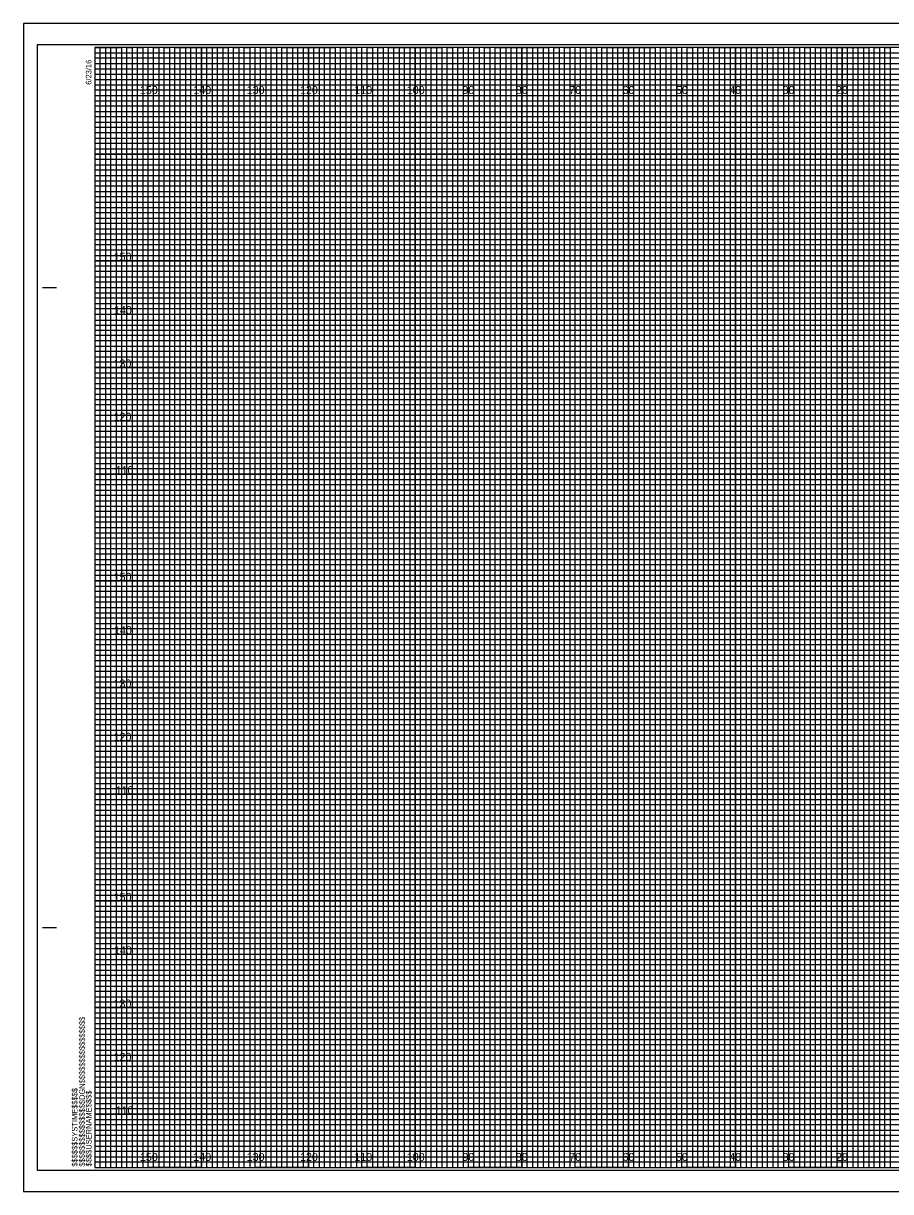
# Model space of a CAD drawing. Extents: x -13 to 323, y -5 to 2634.
# Drawn here: x -13.4 to 149.1, y 215.5 to 434.5 of the extents above; entities that cross this region are included whole.
import ezdxf

# ---------------------------------------------------------------- set-up
doc = ezdxf.new("R2010")
doc.units = 0
for name, color, linetype in [('Exist Cross Section Cell', 7, 'Continuous'), ('Exist XS Center Line Elevation Label', 7, 'Continuous'), ('Exist XS Ground Line', 7, 'Continuous'), ('Prop CMT Pvmt Course 1 Wedge', 7, 'Continuous'), ('Prop CMT Pvmt Course 2', 7, 'Continuous'), ('Prop CMT Pvmt Course 2 Wedge', 7, 'Continuous'), ('Prop CMT Pvmt Course 3', 7, 'Continuous'), ('Prop CMT Shld Paved Course 1', 7, 'Continuous'), ('Prop CMT Shld Paved Course 2', 7, 'Continuous'), ('Prop CMT Subgrade Earthwork', 7, 'Continuous'), ('Scratch_Level_0', 7, 'Continuous')]:
    doc.layers.add(name, color=color, linetype=linetype)

msp = doc.modelspace()

# ---------------------------------------------------------------- linework, layer by layer
at = {"layer": 'Exist XS Center Line Elevation Label'}
for points in [[(0, 430), (5, 430), (5, 220), (15, 220), (15, 430), (25, 430), (25, 220), (35, 220), (35, 430), (45, 430), (45, 220), (55, 220), (55, 430), (65, 430), (65, 220), (75, 220), (75, 430), (85, 430), (85, 220), (95, 220), (95, 430), (105, 430), (105, 220), (115, 220), (115, 430), (125, 430), (125, 220), (135, 220), (135, 430), (145, 430), (145, 220), (155, 220)], [(0, 425), (275, 425)], [(0, 405), (320, 405), (320, 415), (0, 415)], [(0, 385), (320, 385), (320, 395), (0, 395)], [(0, 365), (320, 365), (320, 375), (0, 375)], [(0, 345), (320, 345), (320, 355), (0, 355)], [(0, 325), (320, 325), (320, 335), (0, 335)], [(0, 305), (320, 305), (320, 315), (0, 315)], [(0, 285), (320, 285), (320, 295), (0, 295)], [(0, 265), (320, 265), (320, 275), (0, 275)], [(0, 245), (320, 245), (320, 255), (0, 255)], [(0, 225), (320, 225), (320, 235), (0, 235)]]:
    msp.add_lwpolyline(points, dxfattribs=at)
at = {"layer": 'Exist XS Ground Line'}
for p, q in [((10, 430), (0, 430)), ((10, 220), (10, 430)), ((30, 430), (20, 430)), ((20, 430), (20, 220)), ((30, 220), (30, 430)), ((50, 430), (40, 430)), ((40, 430), (40, 220)), ((50, 220), (50, 430)), ((70, 430), (60, 430)), ((60, 430), (60, 220)), ((70, 220), (70, 430)), ((90, 430), (80, 430)), ((80, 430), (80, 220)), ((90, 220), (90, 430)), ((110, 430), (100, 430)), ((100, 430), (100, 220)), ((110, 220), (110, 430)), ((130, 430), (120, 430)), ((120, 430), (120, 220)), ((130, 220), (130, 430)), ((150, 430), (140, 430)), ((140, 430), (140, 220)), ((20, 220), (10, 220)), ((40, 220), (30, 220)), ((60, 220), (50, 220)), ((80, 220), (70, 220)), ((100, 220), (90, 220)), ((120, 220), (110, 220)), ((140, 220), (130, 220))]:
    msp.add_line(p, q, dxfattribs=at)
for points in [[(0, 420), (320, 420), (320, 410), (0, 410)], [(0, 400), (320, 400), (320, 390), (0, 390)], [(0, 380), (320, 380), (320, 370), (0, 370)], [(0, 360), (320, 360), (320, 350), (0, 350)], [(0, 340), (320, 340), (320, 330), (0, 330)], [(0, 320), (320, 320), (320, 310), (0, 310)], [(0, 300), (320, 300), (320, 290), (0, 290)], [(0, 280), (320, 280), (320, 270), (0, 270)], [(0, 260), (320, 260), (320, 250), (0, 250)], [(0, 240), (320, 240), (320, 230), (0, 230)]]:
    msp.add_lwpolyline(points, dxfattribs=at)
at = {"layer": 'Prop CMT Pvmt Course 1 Wedge'}
for p, q in [((323.3, 434.5), (-13.4, 434.5)), ((-13.4, 434.5), (-13.4, 215.5)), ((-13.4, 215.5), (323.3, 215.5))]:
    msp.add_line(p, q, dxfattribs=at)
at = {"layer": 'Prop CMT Pvmt Course 2'}
msp.add_lwpolyline([(-13.4, 215.5), (323.3, 215.5), (323.3, 434.5), (-13.4, 434.5)], close=True, dxfattribs=at)
at = {"layer": 'Prop CMT Pvmt Course 3'}
msp.add_lwpolyline([(-10.8, 219.5), (322.4, 219.5), (322.4, 430.5), (-10.8, 430.5)], close=True, dxfattribs=at)
at = {"layer": 'Prop CMT Shld Paved Course 1'}
for p, q in [((-9.8, 385), (-7.3, 385)), ((-9.7, 385), (-7.2, 385)), ((-9.8, 265), (-7.3, 265)), ((-9.7, 265), (-7.2, 265)), ((0, 220), (0, 220)), ((0, 220), (0, 220)), ((0, 220), (0, 220)), ((0, 220), (0, 220)), ((0, 220), (0, 220)), ((0, 220), (0, 220)), ((0, 220), (0, 220))]:
    msp.add_line(p, q, dxfattribs=at)
msp.add_lwpolyline([(320, 430), (0, 430), (0, 220), (320, 220)], close=True, dxfattribs=at)
at = {"layer": 'Prop CMT Shld Paved Course 2'}
for points in [[(0, 220), (1, 220), (1, 430), (2, 430), (2, 220)], [(2, 220), (3, 220), (3, 430), (4, 430), (4, 220)], [(5, 220), (6, 220), (6, 430), (7, 430), (7, 220)], [(7, 220), (8, 220), (8, 430), (9, 430), (9, 220)], [(10, 220), (11, 220), (11, 430), (12, 430), (12, 220)], [(12, 220), (13, 220), (13, 430), (14, 430), (14, 220)], [(15, 220), (16, 220), (16, 430), (17, 430), (17, 220)], [(17, 220), (18, 220), (18, 430), (19, 430), (19, 220)], [(20, 220), (21, 220), (21, 430), (22, 430), (22, 220)], [(22, 220), (23, 220), (23, 430), (24, 430), (24, 220)], [(25, 220), (26, 220), (26, 430), (27, 430), (27, 220)], [(27, 220), (28, 220), (28, 430), (29, 430), (29, 220)], [(30, 220), (31, 220), (31, 430), (32, 430), (32, 220)], [(32, 220), (33, 220), (33, 430), (34, 430), (34, 220)], [(35, 220), (36, 220), (36, 430), (37, 430), (37, 220)], [(37, 220), (38, 220), (38, 430), (39, 430), (39, 220)], [(40, 220), (41, 220), (41, 430), (42, 430), (42, 220)], [(42, 220), (43, 220), (43, 430), (44, 430), (44, 220)], [(45, 220), (46, 220), (46, 430), (47, 430), (47, 220)], [(47, 220), (48, 220), (48, 430), (49, 430), (49, 220)], [(50, 220), (51, 220), (51, 430), (52, 430), (52, 220)], [(52, 220), (53, 220), (53, 430), (54, 430), (54, 220)], [(55, 220), (56, 220), (56, 430), (57, 430), (57, 220)], [(57, 220), (58, 220), (58, 430), (59, 430), (59, 220)], [(60, 220), (61, 220), (61, 430), (62, 430), (62, 220)], [(62, 220), (63, 220), (63, 430), (64, 430), (64, 220)], [(65, 220), (66, 220), (66, 430), (67, 430), (67, 220)], [(67, 220), (68, 220), (68, 430), (69, 430), (69, 220)], [(70, 220), (71, 220), (71, 430), (72, 430), (72, 220)], [(72, 220), (73, 220), (73, 430), (74, 430), (74, 220)], [(75, 220), (76, 220), (76, 430), (77, 430), (77, 220)], [(77, 220), (78, 220), (78, 430), (79, 430), (79, 220)], [(80, 220), (81, 220), (81, 430), (82, 430), (82, 220)], [(82, 220), (83, 220), (83, 430), (84, 430), (84, 220)], [(85, 220), (86, 220), (86, 430), (87, 430), (87, 220)], [(87, 220), (88, 220), (88, 430), (89, 430), (89, 220)], [(90, 220), (91, 220), (91, 430), (92, 430), (92, 220)], [(92, 220), (93, 220), (93, 430), (94, 430), (94, 220)], [(95, 220), (96, 220), (96, 430), (97, 430), (97, 220)], [(97, 220), (98, 220), (98, 430), (99, 430), (99, 220)], [(100, 220), (101, 220), (101, 430), (102, 430), (102, 220)], [(102, 220), (103, 220), (103, 430), (104, 430), (104, 220)], [(105, 220), (106, 220), (106, 430), (107, 430), (107, 220)], [(107, 220), (108, 220), (108, 430), (109, 430), (109, 220)], [(110, 220), (111, 220), (111, 430), (112, 430), (112, 220)], [(112, 220), (113, 220), (113, 430), (114, 430), (114, 220)], [(115, 220), (116, 220), (116, 430), (117, 430), (117, 220)], [(117, 220), (118, 220), (118, 430), (119, 430), (119, 220)], [(120, 220), (121, 220), (121, 430), (122, 430), (122, 220)], [(122, 220), (123, 220), (123, 430), (124, 430), (124, 220)], [(125, 220), (126, 220), (126, 430), (127, 430), (127, 220)], [(127, 220), (128, 220), (128, 430), (129, 430), (129, 220)], [(130, 220), (131, 220), (131, 430), (132, 430), (132, 220)], [(132, 220), (133, 220), (133, 430), (134, 430), (134, 220)], [(135, 220), (136, 220), (136, 430), (137, 430), (137, 220)], [(137, 220), (138, 220), (138, 430), (139, 430), (139, 220)], [(140, 220), (141, 220), (141, 430), (142, 430), (142, 220)], [(142, 220), (143, 220), (143, 430), (144, 430), (144, 220)], [(145, 220), (146, 220), (146, 430), (147, 430), (147, 220)], [(147, 220), (148, 220), (148, 430), (149, 430), (149, 220)]]:
    msp.add_lwpolyline(points, dxfattribs=at)
at = {"layer": 'Prop CMT Subgrade Earthwork'}
for p, q in [((10, 220), (10, 430)), ((20, 220), (20, 430)), ((30, 220), (30, 430)), ((40, 220), (40, 430)), ((50, 220), (50, 430)), ((60, 220), (60, 430)), ((70, 220), (70, 430)), ((80, 220), (80, 430)), ((90, 220), (90, 430)), ((100, 220), (100, 430)), ((110, 220), (110, 430)), ((120, 220), (120, 430)), ((130, 220), (130, 430)), ((140, 220), (140, 430)), ((0, 420), (320, 420)), ((0, 410), (320, 410)), ((0, 400), (320, 400)), ((0, 390), (320, 390)), ((0, 380), (320, 380)), ((0, 370), (320, 370)), ((0, 360), (320, 360)), ((0, 350), (320, 350)), ((0, 340), (320, 340)), ((0, 330), (320, 330)), ((0, 320), (320, 320)), ((0, 310), (320, 310)), ((0, 300), (320, 300)), ((0, 290), (320, 290)), ((0, 280), (320, 280)), ((0, 270), (320, 270)), ((0, 260), (320, 260)), ((0, 250), (320, 250)), ((0, 240), (320, 240)), ((0, 230), (320, 230))]:
    msp.add_line(p, q, dxfattribs=at)
at = {"layer": 'Scratch_Level_0'}
for p, q in [((0, 429), (260, 429)), ((260, 427.98), (0, 427.98)), ((0, 427.98), (0, 427)), ((0, 427), (260, 427)), ((260, 425.89), (0, 425.89)), ((0, 425.89), (0, 424)), ((0, 424), (320, 424))]:
    msp.add_line(p, q, dxfattribs=at)
for points in [[(0, 423), (270, 423), (320, 423), (320, 422), (0, 422)], [(0, 421), (320, 421), (320, 419), (0, 419)], [(0, 418), (320, 418), (320, 417), (0, 416.98)], [(0, 416), (320, 416), (320, 414), (0, 414)], [(0, 413), (320, 413), (320, 412), (0, 412)], [(0, 411), (320, 411), (320, 409), (0, 409)], [(0, 408), (320, 408), (320, 407), (0, 407)], [(0, 406), (320, 406), (320, 404), (0, 404)], [(0, 403), (320, 403), (320, 402), (0, 402)], [(0, 401), (320, 401), (320, 399), (0, 399)], [(0, 398), (320, 398), (320, 397), (0, 397)], [(0, 396), (320, 396), (320, 393.95), (320, 393), (320, 392), (0, 392)], [(0, 394), (320, 394), (320, 393), (0, 393)], [(0, 391), (320, 391), (320, 389), (0, 389.03)], [(0, 389.03), (320, 389), (320, 388), (0, 388)], [(0, 387), (320, 387), (320, 386), (0, 386)], [(0, 384), (320, 384), (320, 383), (0, 383)], [(0, 382), (320, 382), (320, 381), (0, 381)], [(-0.07, 378.89), (320, 378.89), (320, 377.88), (-0.07, 377.88)], [(0, 377), (320, 377), (320, 376), (0, 376)], [(0, 374), (320, 374), (320, 373), (0, 373)], [(0, 372), (320, 372), (320, 371), (0, 371)], [(0, 369), (320, 369), (320, 368), (0, 368)], [(0, 367), (320, 367), (320, 366), (0, 366)], [(0, 364), (320, 364), (320, 363), (0, 363)], [(0, 362), (320, 362), (320, 361), (0, 361)], [(0, 359), (320, 359), (319.99, 357.98), (0, 358)], [(0, 357), (320, 357), (320, 356), (0, 356)], [(0, 354), (320, 354), (320, 353), (0, 353)], [(0, 352), (320, 352), (320, 351), (0, 351)], [(0, 349), (320, 349), (320, 348), (0, 348)], [(0, 347), (320, 347), (320, 346), (0, 346)], [(0, 344), (320, 344), (320, 343), (0, 343)], [(0, 342), (320, 342), (320, 341), (0, 341)], [(0, 339), (320, 339), (320, 338), (0, 338)], [(0, 336.99), (320.07, 336.91), (320, 336), (0, 336)], [(0, 334), (320, 334), (320, 333), (0, 333)], [(0, 332), (320, 332), (320, 331), (0, 331)], [(0, 329), (320, 329), (320, 328), (0, 328)], [(0, 327), (320, 327), (320, 326), (0, 326)], [(0, 324), (320, 324), (320, 323), (0, 323)], [(0, 322), (320, 322), (320, 321), (0, 321)], [(0, 319), (320, 319), (320, 318), (0, 318)], [(0, 317), (320, 317), (320, 316), (0, 316)], [(0, 314), (320, 314), (320, 313), (0, 313)], [(0, 312), (320, 312), (320, 311), (0, 311)], [(0, 309), (320, 309), (320, 308), (0, 308)], [(0, 307), (320, 307), (320, 306), (0, 306)], [(0, 304), (320, 304), (320, 303), (0, 303)], [(0, 302), (320, 302), (320, 301), (0, 301)], [(0, 299), (320, 299), (319.99, 297.98), (0, 298)], [(0, 297), (320, 297), (320, 296), (0, 296)], [(0, 294), (320, 294), (320, 293), (0, 293)], [(0, 292), (320, 292), (320, 291), (0, 291)], [(0, 289), (320, 289), (320, 288), (0, 288)], [(0, 287), (320, 287), (320, 286), (0, 286)], [(0, 284), (320, 284), (320, 283), (0, 283)], [(0, 282), (320, 282), (320, 281), (0, 281)], [(0, 279), (320, 279), (320, 278), (0, 278)], [(0, 276.99), (320.07, 276.91), (320, 276), (0, 276)], [(0, 274), (320, 274), (320, 273), (0, 273)], [(0, 272), (320, 272), (320, 271), (0, 271)], [(0, 269), (320, 269), (320, 268), (0, 268)], [(0, 267), (320, 267), (320, 266), (0, 266)], [(0, 264), (320, 264), (320, 263), (0, 263)], [(0, 262), (320, 262), (320, 261), (0, 261)], [(0, 259), (320, 259), (320, 258), (0, 258)], [(0, 257), (320, 257), (320, 256), (0, 256)], [(0, 254), (320, 254), (320, 253), (0, 253)], [(0, 252), (320, 252), (320, 251), (0, 251)], [(0, 249), (320, 249), (320, 248), (0, 248)], [(0, 247), (320, 247), (320, 246), (0, 246)], [(0, 244), (320, 244), (320, 243), (0, 243)], [(0, 242), (320, 242), (320, 241), (0, 241)], [(0, 239), (320, 239), (320, 238), (0, 238)], [(0, 237), (320, 237), (320, 236), (0, 236)], [(0, 234), (320, 234), (320, 233), (0, 233)], [(0, 232), (320, 232), (320, 231), (0, 231)], [(0, 229), (320, 229), (320, 228), (0, 228)], [(0, 227), (320, 227), (320, 226), (0, 226)], [(0, 224), (320, 224), (320, 223), (0, 223)], [(0, 222), (320, 222), (320, 221), (0, 221)]]:
    msp.add_lwpolyline(points, dxfattribs=at)

# ---------------------------------------------------------------- texts
at = {"layer": 'Exist Cross Section Cell'}
for s, p in [('150', (8.44, 421.25)), ('140', (18.44, 421.25)), ('130', (28.44, 421.25)), ('120', (38.44, 421.25)), ('110', (48.62, 421.25)), ('100', (58.44, 421.25)), ('90', (68.86, 421.25)), ('80', (78.86, 421.25)), ('70', (88.86, 421.25)), ('60', (98.86, 421.25)), ('50', (108.86, 421.25)), ('40', (118.86, 421.25)), ('30', (128.86, 421.25)), ('20', (138.86, 421.25)), ('150', (8.44, 221.25)), ('140', (18.44, 221.25)), ('130', (28.44, 221.25)), ('120', (38.44, 221.25)), ('110', (48.62, 221.25)), ('100', (58.44, 221.25)), ('90', (68.86, 221.25)), ('80', (78.86, 221.25)), ('70', (88.86, 221.25)), ('60', (98.86, 221.25)), ('50', (108.86, 221.25)), ('40', (118.86, 221.25)), ('30', (128.86, 221.25)), ('20', (138.86, 221.25))]:
    msp.add_text(s, height=1.5, dxfattribs=at).set_placement(p)
at = {"layer": 'Prop CMT Pvmt Course 2 Wedge'}
for s, p in [('150', (3.52, 390)), ('140', (3.57, 380)), ('130', (3.49, 370)), ('120', (3.5, 360)), ('110', (3.88, 350)), ('150', (3.52, 330)), ('140', (3.57, 320)), ('130', (3.49, 310)), ('120', (3.5, 300)), ('110', (3.88, 290)), ('150', (3.52, 270)), ('140', (3.57, 260)), ('130', (3.49, 250)), ('120', (3.5, 240)), ('110', (3.88, 230))]:
    msp.add_text(s, height=1.5, dxfattribs=at).set_placement(p)
at = {"layer": 'Prop CMT Shld Paved Course 1'}
for s, p in [('6/23/16', (-0.65, 423)), ('$$$$$$$$$$$$$$$$DGN$$$$$$$$$$$$$$$$', (-1.88, 220.18)), ('$$$$$$SYSTIME$$$$$', (-3.26, 220.18)), ('$$$$USERNAME$$$$', (-0.62, 220.23))]:
    msp.add_text(s, height=1.05, rotation=90, dxfattribs=at).set_placement(p)

doc.saveas('drawing.dxf')
